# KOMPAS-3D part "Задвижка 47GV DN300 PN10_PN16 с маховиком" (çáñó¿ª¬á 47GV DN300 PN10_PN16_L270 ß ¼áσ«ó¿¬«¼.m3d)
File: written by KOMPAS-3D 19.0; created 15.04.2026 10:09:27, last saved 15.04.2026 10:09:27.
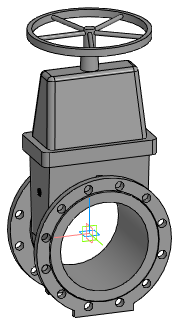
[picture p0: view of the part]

Document properties: Автор: Евгений; Полное имя файла: Z:\3.Личные\kachalov\3d для проектировщиков\2.1 Тип 47GV, 47GV.Z\Задвижка 47GV_DN40-DN600\stp_Задвижка 47GV\Задвижка 47GV DN300 PN10_PN16_L270 с маховиком.m3d

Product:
- Part/product: Задвижка 47GV DN300 PN10_PN16 с маховиком

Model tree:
1. Операция без истории:1  (labels: Задвижка 47GV DN300 PN10_PN16 с маховиком)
